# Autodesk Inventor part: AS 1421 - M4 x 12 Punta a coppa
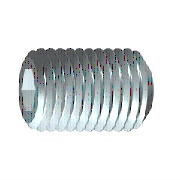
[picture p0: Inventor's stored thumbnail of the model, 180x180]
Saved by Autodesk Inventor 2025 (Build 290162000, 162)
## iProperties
Created: 2024-01
Part Number: AS 1421 - M4 x 12 Punta a coppa
Material: Acciaio, Dolce
Description: Viti di arresto ad esagono incassato metriche ISO
Document SubType Name: Modeling
Standard: AS 1421
Designer: R5800u
Standards Organization: AS
Language: it-IT
Size Designation: M4 x 12 Punta a coppa
Categories: <MemberInstance><Categories><Category DisplayName="Elementi di fissaggio" InternalName="e4da775c-781d-43d5-af7c-5136215cf5a6" Mnemonic="FSTN"><Category DisplayN
Density: 7.85 g/cm^3
Appearance: Semilucidato
IsCustomPart: 0
Author: R5800u
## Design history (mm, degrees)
revolve "Corpo" stored, may be unused: angle "d6" = 90 deg
sketch "Schizzo2"
  geometry: L1 (1.155, 0)-(0.577, -1); L2 (0.577, -1)-(-0.577, -1); L3 (-0.577, -1)-(-1.155, 0); L4 (-1.155, 0)-(-0.577, 1); L5 (-0.577, 1)-(0.577, 1); L6 (0.577, 1)-(1.155, 0); C1 r 2 at (0, 0) reference; A1 r 1.155 centre (0, 0) between (1.155, 0) and (0.577, -1) reference; 1 further point
  constraints: 12 end point, 2 point on circle, 1 coincident, 1 horizontal, 11 other
extrude "Intaglio" join sketch "Schizzo2" distance "d8" = 2.5 (= INTI); taper "d9" = 0 deg
workaxis "Work Axis1"
workplane "Work Plane1"
body "Solid1"
chamfer "Smusso1" distance "d10" = 1.15 (= -0.5 x SPD + 0.5 x NND); stored, may be unused: angle "d11" = 45 deg (= FAWI), second distance "d33" = 1.15 (= -0.5 x SPD + 0.5 x NND)
feature "Filettatura" dims "d14" = 12 (= NLG), "d15" = 0
chamfer "Smusso2" distance "d12" = 0.42941 (= -0.5 x GD1 + 0.5 x NND); stored, may be unused: angle "d13" = 45 deg (= FAWI), second distance "d34" = 0.42941 (= -0.5 x GD1 + 0.5 x NND)
sketch "Schizzo1"
  geometry: L1 (0.396, 0)-(8.833, 0); L2 (12, 1.155)-(12, 2); L3 (12, 2)-(0, 2); L4 (12, 1.155)-(9.5, 1.155); L5 (9.5, 1.155)-(8.833, 0); L6 (0, 0.85)-(0.396, 0); L7 (0, -0.4)-(0, 2.4) reference; L8 (0, 0.85)-(0, 2); 1 further point
  constraints: 14 end point, 2 parallel, 2 perpendicular, 2 point on line, 1 horizontal
  dimensions: "d0" = 2.5 distance of L2.start L4.end (= INTI); "d1" = 60 deg angle of L5 L1; "d2" = 4 diameter of L3 L1 (= NND); "d3" = 2.3094 diameter of L4 L1 (= 1.1547 x SW); "d4" = 12 distance from line of L2 L6.start (= NLG); "d5" = 65 deg angle of L1 L6 (= 0.5 x ANG); "d7" = 1.7 diameter of L6.start L1 (= SPD)
other parameters: "NND" = 4 [user parameter; used in 5 equation terms], "NLG" = 12 [user parameter; used in 2 equation terms], "INTI" = 2.5 [user parameter; used in 2 equation terms], "FAWI" = 45 deg [user parameter; used in 2 equation terms], "SW" = 2 [user parameter; used in 2 equation terms], "GD1" = 3.14117 (= THREADDIA - 1.2269 x PTC) [user parameter; used in 2 equation terms], "ANG" = 130 deg [user parameter; used in 1 equation term], "FAWI1" = 60 deg [user parameter], "SPD" = 1.7 [user parameter; used in 3 equation terms], "d16" = 0, "d35" = 0, "d37" = 0, "GUL" = 0.42941 (= 0.61345 x PTC) [user parameter], "TPU" = 14.28571 (computed from PTC) [user parameter], "TOA" = 30 deg [user parameter], "THREADDIA" = 4 [user parameter; used in 1 equation term], "PTC" = 0.7 [user parameter; used in 4 equation terms], "GAL" = 0.42941 (= 0.61345 x PTC) [user parameter], "E0" = 2.31 (= 1.155 x SW) [user parameter]
